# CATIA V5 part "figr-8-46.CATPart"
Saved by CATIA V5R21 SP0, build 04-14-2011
Part number: Part1
Bounding box of the stored display mesh (mm): x -46.99 to 46.99, y -111.421 to 111.421, z 0 to 30
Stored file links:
  D:\CATIA V5R21 E-RESOURCES\CATIA-V5R21\catia-v5r21-prt\c08-catia-v5r20-prt\c08-catia-v5r21-figr-8-46.CATPart
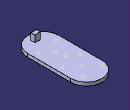
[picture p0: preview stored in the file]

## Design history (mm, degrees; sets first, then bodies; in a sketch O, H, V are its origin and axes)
Set1
  Point1: type OnPlane, Support end face of Pad1, H -29.651, V 16.503, Direction (1, 0, 0)
  Point2: type OnPlane, Support end face of Pad1, H 32.527, V 24.633, Direction (1, 0, 0)
  Point3: type OnPlane, Support end face of Pad1, H -0.958, V 47.624, Direction (1, 0, 0)
  Point4: type OnPlane, Support end face of Pad1, H -32.979, V 77.546, Direction (1, 0, 0)
  Point5: type OnPlane, Support end face of Pad1, H -4.198, V -0.555, Direction (1, 0, 0)
  Point6: type OnPlane, Support end face of Pad1, H 24.642, V 78.69, Direction (1, 0, 0)
  Point7: type OnPlane, Support end face of Pad1, H 1.401, V -27.141, Direction (1, 0, 0)
  Point8: type OnPlane, Support end face of Pad1, H -28.672, V -54.785, Direction (1, 0, 0)
  Point9: type OnPlane, Support end face of Pad1, H 29.834, V -50.327, Direction (1, 0, 0)
Body1 (main body)
  Sketch1 on xy-plane, origin (0, 0, 0), H (1, 0, 0), V (0, 1, 0)
    construction line L1 (-46.9897, 64.4313) -> (46.9897, 64.4313)
    line L2 (46.9897, 64.4313) -> (46.9897, -64.4313)
    construction line L3 (46.9897, -64.4313) -> (-46.9897, -64.4313)
    line L4 (-46.9897, -64.4313) -> (-46.9897, 64.4313)
    axis line L5 (46.9897, -64.4313) -> (-46.9897, 64.4313)
    arc A1 centre (0, 64.4313) radius 46.9897 from (-46.9897, 64.4313) to (46.9897, 64.4313) cw
    arc A2 centre (0, -64.4313) radius 46.9897 from (-46.9897, -64.4313) to (46.9897, -64.4313) ccw
    point P7 (0, -111.4211)
    length L3 = 93.9795
    length L2 = 128.8627
    horizontal: L1 H, L3 H
    vertical: L2 V, L4 V
    midpoint: O L5
    tangency: A1 L2, A2 L4
    coincidence: A2 P7, P7 V
  Pad1: profile Sketch1, direction (0, 0, 1), length 10
  Sketch2 on face of Pad1, origin (0, 0, 10), H (1, 0, 0), V (0, 1, 0)
    line L1 (-8.4317, -82.0722) -> (8.3047, -82.0722)
    line L2 (8.3047, -82.0722) -> (8.3047, -93.8638)
    line L3 (8.3047, -93.8638) -> (-8.4317, -93.8638)
    line L4 (-8.4317, -93.8638) -> (-8.4317, -82.0722)
    horizontal: L1 H, L3 H
    vertical: L2 V, L4 V
  Pad2: profile Sketch2, direction (0, 0, 1), length 20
